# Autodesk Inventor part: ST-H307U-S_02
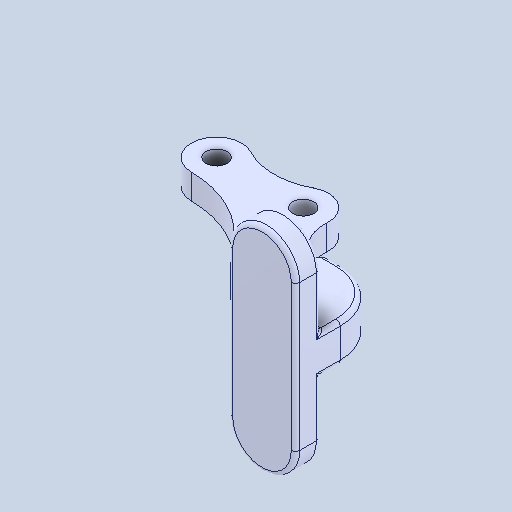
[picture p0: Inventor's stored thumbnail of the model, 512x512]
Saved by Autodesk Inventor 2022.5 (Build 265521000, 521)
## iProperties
Created: 2024-07
Part Number: ST-H307U-S_02
Material: 一般
Document SubType Name: Modeling
Designer: ImaoCorp
Density: 1 g/cm^3
Appearance: 既定
Author: ImaoCorp
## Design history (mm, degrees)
feature "ST-H307U-S_02"
node "ソリッド1"
